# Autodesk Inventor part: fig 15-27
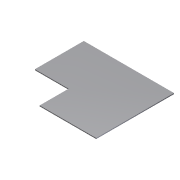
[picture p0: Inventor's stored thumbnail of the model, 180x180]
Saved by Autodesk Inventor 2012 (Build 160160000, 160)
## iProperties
Created: 2005-03
Part Number: fig 15-27
Document SubType Name: Sheet Metal
Designer: CADCIM
Manufacturer: Standard
Standards Organization: Custom
Density: 1 g/cm^3
Sheet Metal Rule: Default
Material: Default
Author: CADCIM
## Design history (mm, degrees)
node "Face1"
  sketch "Sketch1"
    geometry: L1 (29.25, 32.25)-(-19.875, 32.25); L2 (-19.875, 32.25)-(-19.875, 5.625); L3 (-19.875, 5.625)-(-1.5, 5.625); L4 (-1.5, 5.625)-(-1.5, -10.125); L5 (-1.5, -10.125)-(29.25, -10.125); L6 (29.25, -10.125)-(29.25, 32.25)
    constraints: 12 end point, 4 parallel, 1 horizontal, 1 perpendicular
body "Solid1"
face "Plate1" dims "Thickness" = 0.5
other parameters: "BendRadius" = 0.5 (= Thickness), "BendReliefWidth" = 0.5 (= Thickness), "BendReliefDepth" = 0.25 (= 0.5 x Thickness), "CornerReliefSize" = 2 (= 4 x Thickness), "SeamGap" = 0.01, "MinimumRemnant" = 1 (= 2 x Thickness), "TransitionRadius" = 0.5 (= BendRadius), "JacobiRadiusSize" = 0.5 (= Thickness), "GapSize" = 0.5 (= Thickness), "d0" = 0.5 (= BendRadius)
